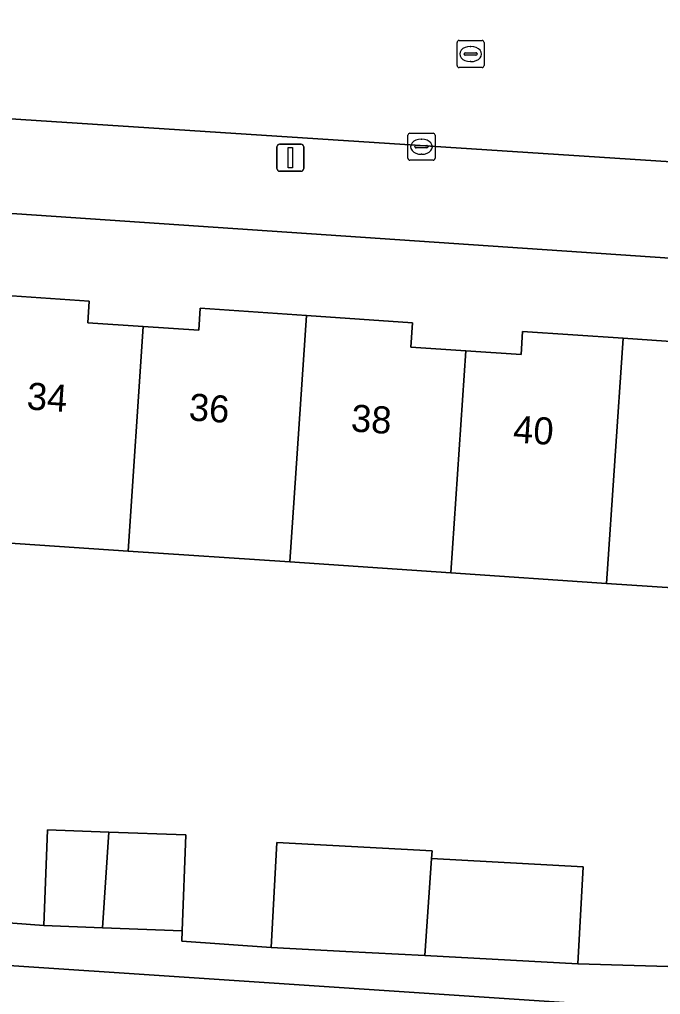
# Model space of a CAD drawing. Extents: x 161848 to 162726, y 385382 to 386521.
# Drawn here: x 162389.22 to 162412.92, y 385424.82 to 385460.85 of the extents above; entities that cross this region are included whole.
import ezdxf

# ---------------------------------------------------------------- set-up
doc = ezdxf.new("R2010")
doc.units = 0
for name, color, linetype in [('IMGEO_Erf', 7, 'Continuous'), ('IMGEO_Kolk', 7, 'Continuous'), ('IMGEO_Lichtmast', 7, 'Continuous'), ('IMGEO_Pand', 7, 'Continuous'), ('IMGEO_Pand_nummerreeks', 7, 'Continuous'), ('IMGEO_Rijbaan_lokaal_open', 7, 'Continuous'), ('IMGEO_Rioolput', 7, 'Continuous'), ('IMGEO_Voetpad_open', 7, 'Continuous')]:
    doc.layers.add(name, color=color, linetype=linetype)

msp = doc.modelspace()

# ---------------------------------------------------------------- linework, layer by layer
at = {"layer": 'IMGEO_Erf'}
for points in [[(162428.108, 385451.016), (162424.152, 385451.285), (162286.568, 385460.627), (162285.504, 385460.702)], [(162387.858, 385450.704), (162391.799, 385450.438), (162391.745, 385449.644), (162393.797, 385449.505), (162395.849, 385449.367), (162395.903, 385450.175), (162399.828, 385449.909), (162403.749, 385449.644), (162403.688, 385448.744), (162405.725, 385448.606), (162407.761, 385448.469), (162407.818, 385449.318), (162411.535, 385449.066), (162415.25, 385448.815)], [(162416.914, 385439.608), (162410.92, 385440.013), (162405.168, 385440.402), (162399.209, 385440.804), (162393.234, 385441.208), (162387.24, 385441.613)], [(162427.854, 385404.175), (162428.958, 385423.219), (162280.836, 385433.091), (162278.626, 385400.728), (162278.251, 385395.589)], [(162383.076, 385427.896), (162390.12, 385427.37), (162390.251, 385430.908), (162392.529, 385430.824), (162395.368, 385430.719), (162395.237, 385427.18), (162395.223, 385426.793), (162398.524, 385426.565), (162398.732, 385430.44), (162401.492, 385430.292), (162404.471, 385430.132), (162404.451, 385429.843), (162410.054, 385429.542), (162409.861, 385425.954), (162414.028, 385425.832)]]:
    msp.add_lwpolyline(points, dxfattribs=at)
at = {"layer": 'IMGEO_Kolk'}
for p, q in [((162403.655, 385456.645), (162404.507, 385456.645)), ((162403.58, 385455.719), (162403.58, 385456.571)), ((162404.068, 385456.425), (162404.093, 385456.425)), ((162404.581, 385456.571), (162404.581, 385455.719)), ((162403.839, 385456.139), (162403.839, 385456.151)), ((162404.277, 385456.102), (162403.879, 385456.102)), ((162403.882, 385456.188), (162404.28, 385456.188)), ((162404.091, 385455.865), (162404.066, 385455.865)), ((162404.323, 385456.151), (162404.323, 385456.139)), ((162404.507, 385455.645), (162403.655, 385455.645))]:
    msp.add_line(p, q, dxfattribs=at)
for points in [[(162403.655, 385456.645), (162404.507, 385456.645)], [(162403.58, 385455.719), (162403.58, 385456.571)], [(162404.581, 385456.571), (162404.581, 385455.719)], [(162404.507, 385455.645), (162403.655, 385455.645)]]:
    msp.add_lwpolyline(points, dxfattribs=at)
for centre, radius, start, end in [((162403.657, 385456.569), 0.0765, 91.552, 178.448), ((162403.657, 385456.569), 0.0765, 91.552, 178.448), ((162404.505, 385456.569), 0.0765, 1.552, 88.448), ((162404.505, 385456.569), 0.0765, 1.552, 88.448), ((162403.879, 385456.148), 0.0403, 85.8775, 175.7526), ((162403.876, 385456.138), 0.0366, 178.938, 274.7102), ((162404.28, 385456.145), 0.043, 264.8664, 352.4533), ((162404.284, 385456.15), 0.0386, 1.7309, 96.639), ((162403.657, 385455.721), 0.0765, 181.552, 268.448), ((162403.657, 385455.721), 0.0765, 181.552, 268.448), ((162404.505, 385455.721), 0.0765, 271.552, 358.448), ((162404.505, 385455.721), 0.0765, 271.552, 358.448)]:
    msp.add_arc(centre, radius, start, end, dxfattribs=at)
for centre, major_axis, ratio, start_param, end_param in [((162404.067, 385456.145), (-0.387, 0.002), 0.722429, 4.712389, 7.853982), ((162404.092, 385456.145), (-0.39, 0.002), 0.717154, 1.570796, 4.712389)]:
    msp.add_ellipse(centre, major_axis=major_axis, ratio=ratio, start_param=start_param, end_param=end_param, dxfattribs=at)
at = {"layer": 'IMGEO_Lichtmast'}
for p, q in [((162398.838, 385456.239), (162399.628, 385456.239)), ((162399.628, 385456.239), (162398.838, 385456.239)), ((162398.738, 385455.339), (162398.738, 385456.139)), ((162398.738, 385456.139), (162398.738, 385455.339)), ((162399.728, 385456.139), (162399.728, 385455.339)), ((162399.728, 385455.339), (162399.728, 385456.139)), ((162399.628, 385455.239), (162398.838, 385455.239)), ((162398.838, 385455.239), (162399.628, 385455.239))]:
    msp.add_line(p, q, dxfattribs=at)
msp.add_lwpolyline([(162399.158, 385456.114), (162399.308, 385456.114), (162399.308, 385455.364), (162399.158, 385455.364), (162399.158, 385456.114)], dxfattribs=at)
for centre, start, end in [((162398.838, 385456.139), 90, 180), ((162398.838, 385456.139), 90, 180), ((162399.628, 385456.139), 0, 90), ((162399.628, 385456.139), 360, 90), ((162398.838, 385455.339), 180, 270), ((162398.838, 385455.339), 180, 270), ((162399.628, 385455.339), 270, 0), ((162399.628, 385455.339), 270, 0)]:
    msp.add_arc(centre, 0.1, start, end, dxfattribs=at)
at = {"layer": 'IMGEO_Pand'}
for points in [[(162393.797, 385449.505), (162391.745, 385449.644), (162391.799, 385450.438), (162387.858, 385450.704), (162387.24, 385441.613), (162393.234, 385441.208)], [(162393.234, 385441.208), (162399.209, 385440.804), (162399.828, 385449.909), (162395.903, 385450.175), (162395.849, 385449.367), (162393.797, 385449.505)], [(162405.725, 385448.606), (162403.688, 385448.744), (162403.749, 385449.644), (162399.828, 385449.909), (162399.209, 385440.804), (162405.168, 385440.402)], [(162405.168, 385440.402), (162410.92, 385440.013), (162411.535, 385449.066), (162407.818, 385449.318), (162407.761, 385448.469), (162405.725, 385448.606)], [(162417.472, 385447.832), (162415.193, 385447.986), (162415.25, 385448.815), (162411.535, 385449.066), (162410.92, 385440.013), (162416.914, 385439.608)], [(162392.529, 385430.824), (162390.251, 385430.908), (162390.12, 385427.37), (162392.289, 385427.289)], [(162392.529, 385430.824), (162392.289, 385427.289), (162395.237, 385427.18), (162395.368, 385430.719)], [(162404.451, 385429.843), (162404.471, 385430.132), (162401.492, 385430.292), (162398.732, 385430.44), (162398.524, 385426.565), (162401.284, 385426.416), (162404.208, 385426.258)], [(162404.451, 385429.843), (162404.208, 385426.258), (162409.861, 385425.954), (162410.054, 385429.542)]]:
    msp.add_lwpolyline(points, close=True, dxfattribs=at)
at = {"layer": 'IMGEO_Rijbaan_lokaal_open'}
msp.add_lwpolyline([(162285.815, 385464.092), (162334.512, 385460.716), (162340.453, 385460.328), (162358.028, 385459.18), (162427.882, 385454.643)], dxfattribs=at)
at = {"layer": 'IMGEO_Rioolput'}
for p, q in [((162405.396, 385459.144), (162405.396, 385459.996)), ((162405.471, 385460.07), (162406.323, 385460.07)), ((162405.884, 385459.85), (162405.909, 385459.85)), ((162406.397, 385459.996), (162406.397, 385459.144)), ((162405.655, 385459.564), (162405.655, 385459.576)), ((162406.093, 385459.527), (162405.695, 385459.527)), ((162405.698, 385459.613), (162406.096, 385459.613)), ((162406.139, 385459.576), (162406.139, 385459.564)), ((162405.907, 385459.29), (162405.882, 385459.29)), ((162406.323, 385459.07), (162405.471, 385459.07))]:
    msp.add_line(p, q, dxfattribs=at)
for points in [[(162405.396, 385459.144), (162405.396, 385459.996)], [(162405.471, 385460.07), (162406.323, 385460.07)], [(162406.397, 385459.996), (162406.397, 385459.144)], [(162406.323, 385459.07), (162405.471, 385459.07)]]:
    msp.add_lwpolyline(points, dxfattribs=at)
for centre, radius, start, end in [((162405.473, 385459.994), 0.0765, 91.552, 178.448), ((162405.473, 385459.994), 0.0765, 91.552, 178.448), ((162406.321, 385459.994), 0.0765, 1.552, 88.448), ((162406.321, 385459.994), 0.0765, 1.552, 88.448), ((162405.695, 385459.573), 0.0403, 85.8775, 175.7526), ((162405.692, 385459.563), 0.0366, 178.938, 274.7102), ((162406.096, 385459.57), 0.043, 264.8664, 352.4533), ((162406.1, 385459.575), 0.0386, 1.7309, 96.639), ((162405.473, 385459.146), 0.0765, 181.552, 268.448), ((162405.473, 385459.146), 0.0765, 181.552, 268.448), ((162406.321, 385459.146), 0.0765, 271.552, 358.448), ((162406.321, 385459.146), 0.0765, 271.552, 358.448)]:
    msp.add_arc(centre, radius, start, end, dxfattribs=at)
for centre, major_axis, ratio, start_param, end_param in [((162405.883, 385459.57), (-0.387, 0.002), 0.722429, 4.712389, 7.853982), ((162405.908, 385459.57), (-0.39, 0.002), 0.717154, 1.570796, 4.712389)]:
    msp.add_ellipse(centre, major_axis=major_axis, ratio=ratio, start_param=start_param, end_param=end_param, dxfattribs=at)
at = {"layer": 'IMGEO_Voetpad_open'}
for points in [[(162427.882, 385454.643), (162358.028, 385459.18), (162340.453, 385460.328), (162334.512, 385460.716), (162285.815, 385464.092)], [(162285.504, 385460.702), (162286.568, 385460.627), (162424.152, 385451.285), (162428.108, 385451.016)], [(162280.836, 385433.091), (162428.958, 385423.219), (162429.053, 385424.859), (162426.05, 385425.033), (162416.476, 385425.669), (162415.971, 385425.703), (162414.028, 385425.832), (162409.861, 385425.954), (162404.208, 385426.258), (162401.284, 385426.416), (162398.524, 385426.565), (162395.223, 385426.793), (162395.237, 385427.18), (162392.289, 385427.289), (162390.12, 385427.37), (162383.076, 385427.896)]]:
    msp.add_lwpolyline(points, dxfattribs=at)

# ---------------------------------------------------------------- texts
at = {"layer": 'IMGEO_Pand_nummerreeks'}
for s, p in [('34', (162389.471, 385446.443)), ('36', (162395.461, 385446.037)), ('38', (162401.455, 385445.63)), ('40', (162407.446, 385445.224))]:
    msp.add_text(s, height=1, rotation=356.1224, dxfattribs=at).set_placement(p)

doc.saveas('drawing.dxf')
